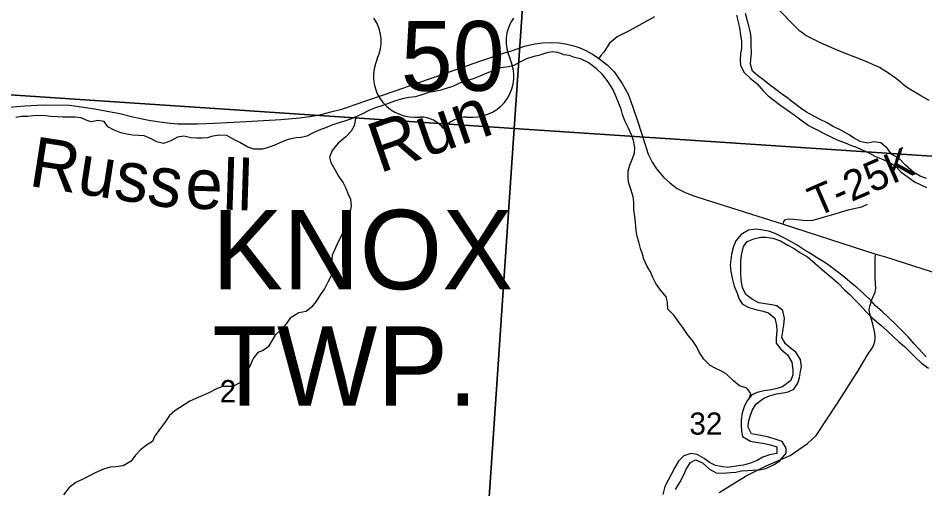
# Model space of a CAD drawing. Extents: x -8.2 to 34, y 0 to 22.
# Drawn here: x 3.458 to 5.17, y 17.043 to 17.933 of the extents above; entities that cross this region are included whole.
import ezdxf

# ---------------------------------------------------------------- set-up
doc = ezdxf.new("R2010")
doc.units = 0
for name, color, linetype in [('GM_X_Corporation', 7, 'Continuous'), ('GM_X_County_Road', 7, 'Continuous'), ('GM_X_Major_River', 7, 'Continuous'), ('GM_X_Minor_River', 7, 'Continuous'), ('GM_X_Minor_River_Text', 7, 'Continuous'), ('GM_X_Section_Text', 7, 'Continuous'), ('GM_X_State_Route', 7, 'Continuous'), ('GM_X_Township_Road', 7, 'Continuous'), ('GM_X_Township_Road_Text', 7, 'Continuous'), ('GM_X_Township_Text', 7, 'Continuous'), ('GM_X_US_Location', 7, 'Continuous'), ('GM_X_US_Route', 7, 'Continuous'), ('GM_X_US_Shield', 7, 'Continuous')]:
    doc.layers.add(name, color=color, linetype=linetype)

msp = doc.modelspace()

# ---------------------------------------------------------------- linework, layer by layer
at = {"layer": 'GM_X_Corporation'}
for points in [[(4.465, 18.749), (4.3947, 17.7241), (3.3856, 17.7912), (3.4438, 18.6343), (3.459, 18.8121)], [(5.4857, 18.6849), (5.4744, 18.5035), (5.4208, 17.6558), (4.3947, 17.7241), (4.465, 18.749)], [(3.3856, 17.7912), (4.3947, 17.7241), (4.3249, 16.693), (3.312, 16.7534)], [(5.4208, 17.6558), (5.3461, 16.6043), (4.3249, 16.693), (4.3947, 17.7241)]]:
    msp.add_lwpolyline(points, close=True, dxfattribs=at)
at = {"layer": 'GM_X_County_Road'}
msp.add_lwpolyline([(4.6598, 17.935), (4.6119, 17.9088), (4.5894, 17.8969), (4.5814, 17.8906), (4.5749, 17.885), (4.5638, 17.8684), (4.5582, 17.8619), (4.5548, 17.8565)], dxfattribs=at)
at = {"layer": 'GM_X_Major_River'}
for points in [[(4.8149, 17.938), (4.8179, 17.9258), (4.8209, 17.9103), (4.8224, 17.9004), (4.8239, 17.8886), (4.8239, 17.8754), (4.8224, 17.8659), (4.8216, 17.8533)], [(4.8418, 17.8549), (4.8429, 17.8662), (4.8425, 17.8826), (4.8422, 17.8947), (4.841, 17.9053), (4.8358, 17.9251), (4.8316, 17.941)], [(4.8216, 17.8533), (4.8224, 17.8439), (4.8284, 17.8306), (4.8406, 17.8192), (4.8539, 17.8082), (4.8649, 17.7953), (4.8747, 17.7854), (4.885, 17.7774), (4.896, 17.7694), (4.9108, 17.7588), (4.9233, 17.7497), (4.9388, 17.7383), (4.9521, 17.7292), (4.9631, 17.7231), (4.9867, 17.7113), (4.9977, 17.706), (5.0079, 17.7014), (5.0197, 17.6968), (5.0299, 17.6927), (5.0413, 17.6885), (5.066, 17.6771), (5.0762, 17.6718), (5.0888, 17.6668), (5.1028, 17.6604), (5.1142, 17.6535), (5.1252, 17.6421), (5.1389, 17.6322), (5.151, 17.6235), (5.1616, 17.6182), (5.1738, 17.6125)], [(5.1734, 17.6296), (5.1616, 17.6337), (5.1499, 17.641), (5.1339, 17.6546), (5.121, 17.6679), (5.1081, 17.6748), (5.099, 17.6869), (5.0873, 17.6972), (5.0736, 17.6987), (5.0618, 17.6964), (5.0485, 17.6995), (5.0368, 17.7056), (5.0262, 17.7124), (5.0129, 17.72), (4.9958, 17.7287), (4.9848, 17.7356), (4.9738, 17.7405), (4.9609, 17.7474), (4.9468, 17.7546), (4.9351, 17.7629), (4.9214, 17.7732), (4.91, 17.7823), (4.8998, 17.7895), (4.8892, 17.7979), (4.8766, 17.807), (4.866, 17.815), (4.8546, 17.8241), (4.8452, 17.8321), (4.841, 17.8454), (4.8418, 17.8549)], [(4.9553, 17.487), (4.9443, 17.4935), (4.9295, 17.5034), (4.9158, 17.511), (4.9018, 17.5189), (4.8878, 17.5254), (4.8775, 17.5292), (4.8642, 17.5322), (4.8513, 17.5338), (4.8373, 17.5319), (4.8236, 17.5239), (4.8133, 17.5118), (4.8087, 17.5012), (4.8053, 17.4867), (4.8038, 17.4765), (4.803, 17.4666), (4.8041, 17.4537), (4.8064, 17.4412), (4.8102, 17.4264), (4.8159, 17.4127), (4.82, 17.4017), (4.8257, 17.3919), (4.8382, 17.3858), (4.8515, 17.3823), (4.8652, 17.3789), (4.8754, 17.3755), (4.8872, 17.3656), (4.8902, 17.352), (4.8906, 17.3425), (4.8898, 17.3277), (4.8898, 17.3182), (4.8985, 17.3072), (4.9107, 17.2962), (4.9194, 17.2825), (4.9213, 17.2681), (4.9213, 17.2586), (4.9171, 17.2479), (4.9015, 17.2362), (4.889, 17.2324), (4.8764, 17.2298), (4.8666, 17.2283), (4.8537, 17.2252), (4.8438, 17.2207), (4.8343, 17.2089), (4.8293, 17.1979), (4.8255, 17.1869), (4.8236, 17.1729), (4.8236, 17.1626), (4.824, 17.152), (4.8262, 17.1421), (4.8414, 17.1334), (4.8513, 17.1315), (4.8646, 17.1292), (4.8786, 17.1265), (4.8908, 17.1227), (4.8907, 17.1098), (4.8767, 17.1072), (4.8645, 17.103), (4.8539, 17.0969), (4.841, 17.0916), (4.8281, 17.0882), (4.8178, 17.0867), (4.7981, 17.0837), (4.7886, 17.0848), (4.7753, 17.0871), (4.7635, 17.0928), (4.7533, 17.1008), (4.7404, 17.108), (4.7282, 17.1103), (4.7149, 17.1054), (4.7054, 17.0955), (4.6982, 17.0838), (4.6917, 17.0716), (4.6796, 17.0474), (4.6754, 17.0326)], [(4.6997, 17.042), (4.708, 17.0564), (4.7153, 17.0697), (4.7195, 17.0803), (4.7275, 17.0932), (4.7373, 17.0978), (4.7502, 17.0921), (4.7639, 17.0803), (4.776, 17.0735), (4.7893, 17.0727), (4.8034, 17.0742), (4.8136, 17.075), (4.8239, 17.0772), (4.8357, 17.078), (4.8451, 17.0784), (4.8584, 17.0791), (4.8698, 17.0818), (4.8858, 17.089), (4.8968, 17.0962), (4.9082, 17.1106), (4.9086, 17.1201), (4.901, 17.1326), (4.8912, 17.136), (4.876, 17.1406), (4.8661, 17.1429), (4.8566, 17.1444), (4.8429, 17.147), (4.8365, 17.16), (4.8376, 17.1698), (4.8407, 17.1804), (4.8445, 17.1915), (4.8514, 17.2032), (4.8662, 17.2146), (4.8768, 17.2188), (4.8905, 17.2225), (4.9026, 17.2244), (4.9125, 17.2267), (4.9228, 17.2316), (4.9304, 17.243), (4.9334, 17.2536), (4.9353, 17.2646), (4.9372, 17.2741), (4.9357, 17.2878), (4.9266, 17.3015), (4.9168, 17.3091), (4.9073, 17.317), (4.9005, 17.3292), (4.902, 17.3406), (4.9043, 17.3531), (4.9051, 17.3648), (4.902, 17.38), (4.8906, 17.3891), (4.8812, 17.3911), (4.8686, 17.3926), (4.8569, 17.3945), (4.8447, 17.4009), (4.8326, 17.4104), (4.8258, 17.4234), (4.8235, 17.4374), (4.8227, 17.4511), (4.8228, 17.4628), (4.8231, 17.4731), (4.8243, 17.4845), (4.8281, 17.5008), (4.835, 17.5103), (4.8475, 17.5156), (4.8604, 17.5186), (4.8699, 17.5186), (4.8832, 17.5167), (4.8976, 17.5117), (4.9116, 17.5037), (4.9234, 17.4973), (4.9344, 17.4897), (4.9485, 17.4813), (4.9633, 17.4692), (4.9765, 17.4578), (4.986, 17.4494)], [(5.1731, 17.2925), (5.1503, 17.3169), (5.1389, 17.3301), (5.1245, 17.3446), (5.115, 17.3544), (5.1025, 17.3662), (5.0896, 17.3784), (5.0775, 17.389), (5.0684, 17.3989), (5.0547, 17.4122), (5.0426, 17.4232), (5.0289, 17.4346), (5.0164, 17.4448), (5.0027, 17.4551), (4.9921, 17.4635), (4.9815, 17.4707), (4.969, 17.4783), (4.9553, 17.487)], [(4.986, 17.4494), (4.9966, 17.4403), (5.0065, 17.4316), (5.0186, 17.4194), (5.0289, 17.4103), (5.0384, 17.4004), (5.049, 17.3898), (5.0589, 17.3784), (5.0718, 17.3659), (5.0873, 17.3522), (5.0994, 17.3416), (5.1104, 17.3313), (5.1211, 17.321), (5.1321, 17.3123), (5.1522, 17.2922), (5.1643, 17.2808), (5.1776, 17.2713)]]:
    msp.add_lwpolyline(points, dxfattribs=at)
at = {"layer": 'GM_X_Minor_River'}
for points in [[(4.8385, 17.2142), (4.8417, 17.2235), (4.8342, 17.2333), (4.8205, 17.2378), (4.8091, 17.2473), (4.7951, 17.2602), (4.7849, 17.2662), (4.7746, 17.2712), (4.7648, 17.2764), (4.753, 17.2882), (4.7439, 17.3014), (4.7394, 17.3124), (4.7329, 17.3219), (4.7223, 17.3348), (4.7132, 17.348), (4.706, 17.3583), (4.6961, 17.3715), (4.6847, 17.3829), (4.6843, 17.3958), (4.682, 17.406), (4.6699, 17.4204), (4.6623, 17.431), (4.6566, 17.4428), (4.6521, 17.4534), (4.646, 17.4632), (4.6399, 17.4769), (4.6369, 17.4864), (4.6334, 17.497), (4.63, 17.5099), (4.627, 17.5201), (4.6254, 17.5315), (4.6239, 17.5463), (4.6228, 17.558), (4.6209, 17.5705), (4.6208, 17.5849), (4.6197, 17.5952), (4.6155, 17.6073), (4.6109, 17.6225), (4.6098, 17.6319), (4.6102, 17.6441), (4.6132, 17.6547), (4.6169, 17.6642), (4.6219, 17.6771), (4.6226, 17.6877), (4.6203, 17.7014), (4.6165, 17.712), (4.6108, 17.7249), (4.604, 17.7385), (4.5994, 17.7506), (4.5968, 17.7605), (4.5914, 17.7741), (4.5873, 17.784), (4.5812, 17.7984), (4.5721, 17.8124), (4.5614, 17.826), (4.5497, 17.8374), (4.5345, 17.8484), (4.5197, 17.8559), (4.5087, 17.8582), (4.4993, 17.862), (4.489, 17.8631), (4.4769, 17.8673), (4.4671, 17.8688), (4.4565, 17.8668), (4.4432, 17.8627), (4.43, 17.8592), (4.4178, 17.8554), (4.4057, 17.8493), (4.394, 17.8432), (4.3838, 17.8406), (4.3698, 17.8383), (4.3599, 17.8348), (4.3433, 17.8284), (4.33, 17.8231), (4.3175, 17.8177), (4.3024, 17.8135), (4.2914, 17.8097), (4.28, 17.804), (4.2664, 17.7998), (4.2565, 17.7964), (4.2448, 17.7941), (4.2331, 17.7922), (4.2221, 17.7884), (4.2081, 17.7838), (4.1956, 17.7823), (4.1831, 17.78), (4.1687, 17.7758), (4.1585, 17.7716), (4.1445, 17.767), (4.1331, 17.7632), (4.1202, 17.7583), (4.1096, 17.7522), (4.0998, 17.748), (4.0873, 17.7423), (4.074, 17.7381), (4.06, 17.7332), (4.0502, 17.7301), (4.0384, 17.7255), (4.0263, 17.7206), (4.0135, 17.7153), (4.0032, 17.7096)], [(4.0032, 17.7096), (3.9926, 17.7069), (3.9828, 17.7061), (3.9676, 17.7031), (3.9536, 17.6974), (3.9426, 17.6928), (3.9302, 17.6882), (3.9196, 17.6848), (3.9033, 17.6851), (3.8915, 17.6885), (3.8767, 17.6976), (3.865, 17.7033), (3.8521, 17.7105), (3.8385, 17.7116), (3.8256, 17.7097), (3.8157, 17.7062), (3.8047, 17.7055), (3.7953, 17.7055), (3.7843, 17.7062), (3.771, 17.7092), (3.7589, 17.7077), (3.746, 17.7008), (3.7324, 17.6959), (3.7195, 17.6985), (3.7093, 17.7046), (3.6956, 17.7099), (3.6854, 17.711), (3.6737, 17.7113), (3.6631, 17.7132), (3.6517, 17.7159), (3.6392, 17.7208), (3.6274, 17.7272), (3.6202, 17.7371), (3.6085, 17.7393), (3.596, 17.7366), (3.5865, 17.7397), (3.577, 17.7442), (3.5649, 17.7457), (3.5536, 17.7453), (3.5429, 17.7457), (3.532, 17.746), (3.5198, 17.7464), (3.5096, 17.7479), (3.4994, 17.7486), (3.4869, 17.7479), (3.4763, 17.7467), (3.4638, 17.7467), (3.4532, 17.7448)], [(4.0954, 17.746), (4.0922, 17.729), (4.0866, 17.7192), (4.0767, 17.7085), (4.062, 17.6964), (4.051, 17.6823), (4.0461, 17.6698), (4.0484, 17.6599), (4.056, 17.6467), (4.0632, 17.6342), (4.0715, 17.6213), (4.0765, 17.6111), (4.081, 17.6001), (4.0856, 17.5902), (4.0871, 17.5773), (4.0849, 17.5675), (4.0818, 17.555), (4.0784, 17.5447), (4.072, 17.5299), (4.0682, 17.5204), (4.0622, 17.5098), (4.0573, 17.4984), (4.0509, 17.4847), (4.0494, 17.4707), (4.0509, 17.4578), (4.0502, 17.448), (4.043, 17.4335), (4.0362, 17.421), (4.0282, 17.4096), (4.0203, 17.3967), (4.012, 17.3865), (4.0021, 17.3781), (3.9881, 17.3758), (3.9718, 17.3659), (3.9639, 17.3549), (3.9556, 17.3454), (3.9435, 17.3337), (3.9355, 17.3211), (3.9302, 17.3116), (3.9204, 17.3048), (3.9106, 17.301), (3.9019, 17.2892), (3.8958, 17.2763), (3.8898, 17.2661), (3.8856, 17.2551), (3.8788, 17.2448), (3.8633, 17.2365), (3.844, 17.2364), (3.8326, 17.2319), (3.8182, 17.2246), (3.8069, 17.2193), (3.7932, 17.2136), (3.7823, 17.2087), (3.7713, 17.2018), (3.7539, 17.1904), (3.7437, 17.1817), (3.735, 17.1688), (3.727, 17.1578), (3.7153, 17.1422), (3.7119, 17.1327), (3.7005, 17.1259), (3.6888, 17.1171), (3.6793, 17.1069), (3.6714, 17.0955), (3.6563, 17.0864), (3.6419, 17.0848), (3.6316, 17.0841), (3.6188, 17.0806), (3.6036, 17.0734), (3.5927, 17.0677), (3.5786, 17.0608), (3.5665, 17.0551), (3.554, 17.0456), (3.5435, 17.032)]]:
    msp.add_lwpolyline(points, dxfattribs=at)
at = {"layer": 'GM_X_State_Route'}
msp.add_lwpolyline([(5.1788, 17.7771), (5.1642, 17.7853), (5.1472, 17.7952), (5.1359, 17.8023), (5.1302, 17.8064), (5.1265, 17.81), (5.1144, 17.8199), (5.1001, 17.8298), (5.0849, 17.8392), (5.0623, 17.8496), (5.0516, 17.8539), (5.0092, 17.87), (4.9733, 17.8859), (4.9507, 17.8972), (4.9444, 17.9005), (4.9398, 17.9038), (4.9343, 17.908), (4.9296, 17.9121), (4.8885, 17.9544)], dxfattribs=at)
at = {"layer": 'GM_X_Township_Road'}
for points in [[(4.9029, 17.5433), (4.9041, 17.5484), (4.9074, 17.5521), (4.9127, 17.5535), (4.9231, 17.5525), (4.9405, 17.5507), (4.9567, 17.5505), (4.9811, 17.557), (4.9983, 17.5619), (5.0257, 17.5705), (5.0396, 17.5736), (5.0513, 17.5761), (5.0622, 17.5808)], [(4.7821, 17.0365), (4.8331, 17.0679), (4.8707, 17.0865), (4.9159, 17.106), (4.9488, 17.1288), (4.965, 17.1437), (5.0055, 17.2051), (5.0448, 17.2677), (5.0636, 17.2986), (5.0722, 17.3108), (5.076, 17.3208), (5.0767, 17.3288), (5.0758, 17.3381), (5.072, 17.3546), (5.0672, 17.3721), (5.0652, 17.3805), (5.0662, 17.3882), (5.0707, 17.4025), (5.0769, 17.4146), (5.0777, 17.4221), (5.0763, 17.441), (5.0765, 17.4712), (5.0768, 17.4804), (5.0781, 17.4867)]]:
    msp.add_lwpolyline(points, dxfattribs=at)
at = {"layer": 'GM_X_US_Route'}
msp.add_lwpolyline([(3.4402, 17.7641), (3.4703, 17.7671), (3.506, 17.769), (3.554, 17.7679), (3.5728, 17.7653), (3.6022, 17.7614), (3.65, 17.7521), (3.6772, 17.7457), (3.7049, 17.74), (3.7246, 17.7368), (3.7449, 17.734), (3.7594, 17.7329), (3.7797, 17.7327), (3.7966, 17.7327), (3.8288, 17.734), (3.8887, 17.7372), (3.9542, 17.7413), (3.9901, 17.7441), (4.0081, 17.7465), (4.0279, 17.7498), (4.0485, 17.7552), (4.0695, 17.7608), (4.0846, 17.7658), (4.0909, 17.7679), (4.1719, 17.796), (4.3317, 17.8518), (4.3767, 17.8667), (4.3914, 17.8713), (4.4143, 17.8795), (4.4336, 17.8838), (4.4483, 17.886), (4.4643, 17.8862), (4.4796, 17.8856), (4.4915, 17.884), (4.5047, 17.881), (4.5172, 17.8769), (4.5302, 17.8715), (4.5428, 17.8646), (4.5495, 17.8603), (4.5548, 17.8565), (4.5706, 17.8445), (4.5837, 17.831), (4.5988, 17.8093), (4.6101, 17.7888), (4.6181, 17.7659), (4.6281, 17.7364), (4.6414, 17.6958), (4.648, 17.6752), (4.6551, 17.6602), (4.6633, 17.6477), (4.6766, 17.6318), (4.6885, 17.6211), (4.7024, 17.6109), (4.7176, 17.6033), (4.7342, 17.5965), (4.7555, 17.5898), (4.9029, 17.5433), (5.0781, 17.4867), (5.0961, 17.4816), (5.2174, 17.4428)], dxfattribs=at)
at = {"layer": 'GM_X_US_Shield'}
for p, q in [((4.2066, 17.7457), (4.2176, 17.7457)), ((4.3054, 17.7457), (4.3164, 17.7457))]:
    msp.add_line(p, q, dxfattribs=at)
for centre, radius, start, end in [((4.0667, 17.8884), 0.0769, 334.5471, 35.0009), ((4.4563, 17.8884), 0.0769, 144.9991, 205.4529), ((4.2057, 17.8226), 0.0769, 154.8319, 270.6383), ((4.3173, 17.8226), 0.0769, 269.3617, 25.1681), ((4.2176, 17.6908), 0.0549, 36.8699, 90), ((4.3054, 17.6908), 0.0549, 90, 143.1301)]:
    msp.add_arc(centre, radius, start, end, dxfattribs=at)

# ---------------------------------------------------------------- texts
at = {"layer": 'GM_X_Minor_River_Text'}
for s, height, rotation, p in [('Run', 0.0947, 19.0677, (4.1403, 17.639)), ('Russ', 0.09469, 351.1868, (3.4759, 17.6158)), ('ell', 0.0947, 358.1882, (3.7727, 17.5731))]:
    msp.add_text(s, height=height, rotation=rotation, dxfattribs=at).set_placement(p)
at = {"layer": 'GM_X_Section_Text'}
for s, height, p in [('2', 0.0419, (3.8386, 17.2068)), ('32', 0.04186, (4.7257, 17.1456))]:
    msp.add_text(s, height=height, rotation=0, dxfattribs=at).set_placement(p)
at = {"layer": 'GM_X_Township_Road_Text'}
msp.add_text('T-25K', height=0.05682, rotation=23.4674, dxfattribs=at).set_placement((4.9659, 17.5564))
at = {"layer": 'GM_X_Township_Text'}
for s, p in [('KNOX', (3.8242, 17.4203)), ('TWP.', (3.8242, 17.2003))]:
    msp.add_text(s, height=0.15, rotation=0, dxfattribs=at).set_placement(p)
at = {"layer": 'GM_X_US_Location'}
for s in ['0', '/']:
    msp.add_text(s, height=0.000189, dxfattribs=at).set_placement((4.2614, 17.8601))
msp.add_text('50', height=0.000189, rotation=0, dxfattribs=at).set_placement((4.2223, 17.8209))
at = {"layer": 'GM_X_US_Shield'}
msp.add_text('50', height=0.13184, dxfattribs=at).set_placement((4.1806, 17.7952))

doc.saveas('drawing.dxf')
